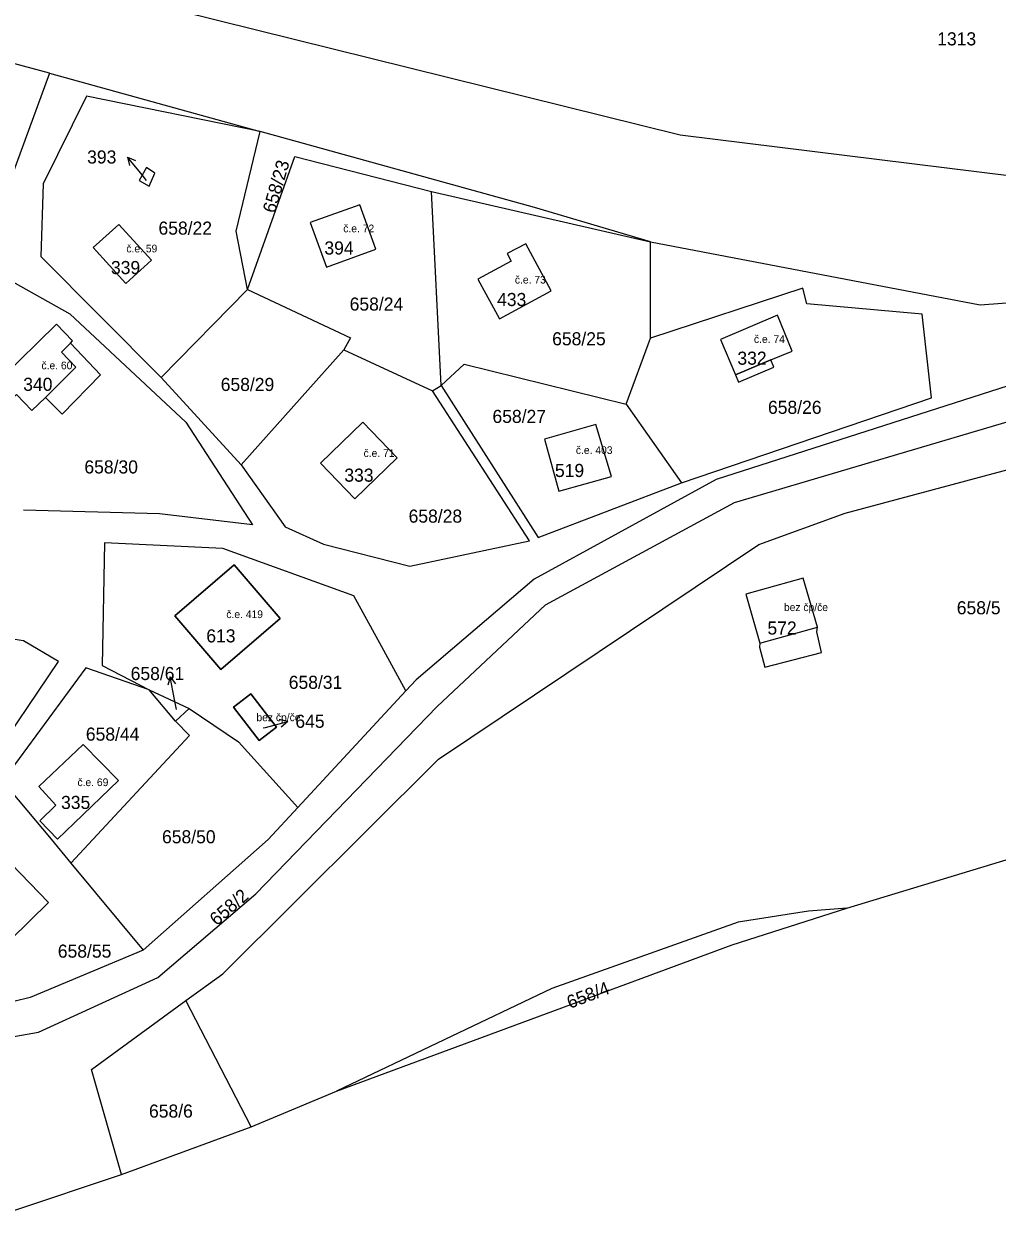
# Model space of a CAD drawing. Extents: x -887272 to -880188, y -1026687 to -1021896.
# Drawn here: x -883771.9 to -883645.6, y -1024180.1 to -1024025.9 of the extents above; entities that cross this region are included whole.
import ezdxf

# ---------------------------------------------------------------- set-up
doc = ezdxf.new("R2010")
doc.units = 0
for name, color, linetype in [('Definiční body', 7, 'Continuous'), ('Hranice parcel', 7, 'Continuous'), ('Parcelní čísla', 7, 'Continuous'), ('Polygon budovy', 7, 'Continuous'), ('Pop  PČ popisy', 7, 'Continuous'), ('Vnitřní kresba', 7, 'Continuous')]:
    doc.layers.add(name, color=color, linetype=linetype)

msp = doc.modelspace()

# ---------------------------------------------------------------- linework, layer by layer
at = {"layer": 'Hranice parcel'}
for p, q in [((-883768.62, -1024032.31), (-883786.49, -1024027.54)), ((-883768.62, -1024032.31), (-883741.24, -1024039.87)), ((-883719.01, -1024047.69), (-883690.56, -1024054.21)), ((-883717.76, -1024072.88), (-883719.01, -1024047.69)), ((-883690.57, -1024066.72), (-883690.56, -1024054.21)), ((-883732.64, -1024057.49), (-883726.22, -1024055.15)), ((-883758.68, -1024059.61), (-883755.37, -1024056.59)), ((-883754.09, -1024071.82), (-883742.91, -1024060.4)), ((-883693.72, -1024075.31), (-883690.57, -1024066.72)), ((-883730.38, -1024068.23), (-883743.71, -1024083.19)), ((-883730.38, -1024068.23), (-883718.88, -1024073.58)), ((-883754.09, -1024071.82), (-883743.71, -1024083.19)), ((-883718.88, -1024073.58), (-883717.76, -1024072.88)), ((-883693.72, -1024075.31), (-883686.57, -1024085.51)), ((-883725.46, -1024106.79), (-883729.08, -1024100.16)), ((-883722.33, -1024112.53), (-883725.46, -1024106.79)), ((-883755.65, -1024112.37), (-883750.48, -1024114.83)), ((-883752.25, -1024116.45), (-883755.65, -1024112.37)), ((-883722.33, -1024112.53), (-883736.35, -1024127.68)), ((-883750.48, -1024114.83), (-883752.25, -1024116.45)), ((-883750.48, -1024114.83), (-883744.05, -1024119.14)), ((-883744.05, -1024119.14), (-883736.35, -1024127.68)), ((-883765.84, -1024134.88), (-883756.44, -1024146.18)), ((-883756.44, -1024146.18), (-883771.09, -1024152.35)), ((-883771.09, -1024152.35), (-883776.38, -1024153.62)), ((-883742.43, -1024169.12), (-883750.88, -1024152.74)), ((-883742.43, -1024169.12), (-883731.34, -1024164.5)), ((-883759.24, -1024175.32), (-883742.43, -1024169.12))]:
    msp.add_line(p, q, dxfattribs=at)
for points in [[(-883751.85, -1024024.16), (-883686.7, -1024040.32), (-883639.5, -1024046.16), (-883608.39, -1024045.1)], [(-883768.62, -1024032.31), (-883776.16, -1024052.87), (-883778.5, -1024053.04), (-883793.12, -1024043.9), (-883786.49, -1024027.54)], [(-883741.24, -1024039.87), (-883763.79, -1024035.29), (-883769.42, -1024046.7), (-883769.72, -1024056.1), (-883754.09, -1024071.82)], [(-883742.91, -1024060.4), (-883744.38, -1024052.83), (-883741.24, -1024039.87)], [(-883690.56, -1024054.21), (-883705.64, -1024049.74), (-883741.24, -1024039.87)], [(-883742.91, -1024060.4), (-883736.76, -1024043.15), (-883719.01, -1024047.69)], [(-883756.02, -1024044.56), (-883756.96, -1024046.24), (-883755.66, -1024047), (-883754.92, -1024045.28), (-883756.02, -1024044.56)], [(-883726.22, -1024055.15), (-883728.32, -1024049.39), (-883734.77, -1024051.7), (-883732.64, -1024057.49)], [(-883755.37, -1024056.59), (-883759.61, -1024051.94), (-883762.92, -1024054.96), (-883758.68, -1024059.61)], [(-883708.66, -1024056.73), (-883712.97, -1024059.05), (-883710.18, -1024064.2), (-883703.46, -1024060.56), (-883706.77, -1024054.45), (-883709.2, -1024055.74), (-883708.66, -1024056.73)], [(-883690.56, -1024054.21), (-883647.79, -1024062.38), (-883637.46, -1024061.6)], [(-883774.14, -1024058.98), (-883765.97, -1024063.54), (-883750.88, -1024077.62), (-883742.25, -1024090.97), (-883754.31, -1024089.52), (-883771.96, -1024089.06)], [(-883846.21, -1024144.12), (-883816.92, -1024155.06), (-883797.46, -1024159.1), (-883785.24, -1024159.54), (-883770.02, -1024156.86), (-883754.54, -1024149.76), (-883741.82, -1024138.86), (-883718.28, -1024114.56), (-883704.22, -1024101.36), (-883679.66, -1024088.08), (-883640.76, -1024076.54), (-883629.62, -1024072.06), (-883617.24, -1024060.68)], [(-883742.91, -1024060.4), (-883729.52, -1024066.69), (-883730.38, -1024068.23)], [(-883686.57, -1024085.51), (-883654.07, -1024074.47), (-883655.32, -1024063.62), (-883670.29, -1024062.28), (-883670.78, -1024060.24), (-883690.57, -1024066.72)], [(-883637.46, -1024061.6), (-883637.26, -1024068), (-883643.06, -1024072.58), (-883682.06, -1024085.08), (-883705.66, -1024098.02), (-883721, -1024111.1), (-883722.33, -1024112.53)], [(-883679.54, -1024071.48), (-883679.14, -1024072.43), (-883674.54, -1024070.47), (-883674.93, -1024069.55), (-883672.16, -1024068.39), (-883674.07, -1024063.75), (-883681.48, -1024066.91), (-883679.54, -1024071.48)], [(-883773.25, -1024074.38), (-883772.9, -1024074.05), (-883770.89, -1024076.11), (-883769.13, -1024074.41), (-883766.95, -1024076.58), (-883761.97, -1024071.47), (-883765.87, -1024067.35), (-883765.62, -1024067.08), (-883767.68, -1024064.92), (-883774.9, -1024072), (-883773.24, -1024073.7), (-883773.59, -1024074.02), (-883773.25, -1024074.38)], [(-883717.76, -1024072.88), (-883714.76, -1024070.1), (-883693.72, -1024075.31)], [(-883750.88, -1024152.74), (-883746.1, -1024149.26), (-883718.1, -1024121.38), (-883676.52, -1024093.5), (-883665.32, -1024089.44), (-883615.24, -1024076.02), (-883604.08, -1024076.62), (-883602.76, -1024070.42), (-883510.71, -1024093.58), (-883510.26, -1024098.08)], [(-883717.76, -1024072.88), (-883705.16, -1024092.62), (-883686.57, -1024085.51)], [(-883743.71, -1024083.19), (-883738.02, -1024091.21), (-883733.04, -1024093.47), (-883721.8, -1024096.35), (-883706.27, -1024093.05), (-883718.88, -1024073.58)], [(-883727.93, -1024077.64), (-883733.43, -1024082.94), (-883728.96, -1024087.58), (-883723.46, -1024082.28), (-883727.93, -1024077.64)], [(-883704.35, -1024079.85), (-883702.47, -1024086.61), (-883695.65, -1024084.69), (-883697.67, -1024077.93), (-883704.35, -1024079.85)], [(-883729.08, -1024100.16), (-883746.09, -1024094.02), (-883761.45, -1024093.29), (-883761.77, -1024109.23), (-883755.65, -1024112.37)], [(-883746.34, -1024109.73), (-883752.31, -1024102.8), (-883744.62, -1024096.17), (-883738.64, -1024103.11), (-883746.34, -1024109.73)], [(-883675.74, -1024109.43), (-883668.37, -1024107.52), (-883668.98, -1024104.85), (-883668.91, -1024104.27), (-883670.74, -1024097.9), (-883678.19, -1024099.96), (-883676.38, -1024106.32), (-883676.42, -1024106.85), (-883675.74, -1024109.43)], [(-883665.07, -1024140.74), (-883601.32, -1024121.4), (-883513.54, -1024098.82), (-883510.26, -1024098.08)], [(-883789.37, -1024125.15), (-883776.68, -1024122.39), (-883767.41, -1024108.72), (-883771.96, -1024106.03), (-883791.15, -1024103.07)], [(-883755.65, -1024112.37), (-883763.88, -1024109.51), (-883774.69, -1024124.26)], [(-883741.4, -1024118.96), (-883744.71, -1024114.63), (-883742.45, -1024112.9), (-883739.14, -1024117.22), (-883741.4, -1024118.96)], [(-883765.84, -1024134.88), (-883750.41, -1024118.33), (-883752.25, -1024116.45)], [(-883767.57, -1024131.79), (-883765.4, -1024129.71), (-883759.62, -1024124.18), (-883764.22, -1024119.5), (-883769.99, -1024124.95), (-883767.76, -1024127.36), (-883769.86, -1024129.38), (-883767.57, -1024131.79)], [(-883774.69, -1024124.26), (-883768.39, -1024131.8), (-883765.84, -1024134.88)], [(-883736.35, -1024127.68), (-883740.2, -1024131.84), (-883756.44, -1024146.18)], [(-883773.62, -1024144.81), (-883768.71, -1024140), (-883773.56, -1024134.99)], [(-883731.34, -1024164.5), (-883679.95, -1024145.51), (-883665.07, -1024140.74)], [(-883665.07, -1024140.74), (-883670.06, -1024141.14), (-883679.17, -1024142.58), (-883703.4, -1024151.16), (-883731.34, -1024164.5)], [(-883759.24, -1024175.32), (-883763.16, -1024161.7), (-883750.88, -1024152.74)], [(-883850.59, -1024159.71), (-883845.76, -1024161.5), (-883773.48, -1024180.1), (-883759.24, -1024175.32)]]:
    msp.add_lwpolyline(points, dxfattribs=at)
at = {"layer": 'Polygon budovy'}
for points in [[(-883728.32, -1024049.39), (-883734.77, -1024051.7), (-883732.64, -1024057.49), (-883726.22, -1024055.15)], [(-883762.92, -1024054.96), (-883758.68, -1024059.61), (-883755.37, -1024056.59), (-883759.61, -1024051.94)], [(-883703.46, -1024060.56), (-883706.77, -1024054.45), (-883709.2, -1024055.74), (-883708.66, -1024056.73), (-883712.97, -1024059.05), (-883710.18, -1024064.2)], [(-883679.54, -1024071.48), (-883674.93, -1024069.55), (-883672.16, -1024068.39), (-883674.07, -1024063.75), (-883681.48, -1024066.91)], [(-883773.59, -1024074.02), (-883773.25, -1024074.38), (-883772.9, -1024074.05), (-883770.89, -1024076.11), (-883769.13, -1024074.41), (-883765.16, -1024070.5), (-883767.03, -1024068.53), (-883765.87, -1024067.35), (-883765.62, -1024067.08), (-883767.68, -1024064.92), (-883774.9, -1024072), (-883773.24, -1024073.7)], [(-883723.46, -1024082.28), (-883727.93, -1024077.64), (-883733.43, -1024082.94), (-883728.96, -1024087.58)], [(-883702.47, -1024086.61), (-883695.65, -1024084.69), (-883697.67, -1024077.93), (-883704.35, -1024079.85)], [(-883738.64, -1024103.11), (-883744.62, -1024096.17), (-883752.31, -1024102.8), (-883746.34, -1024109.73)], [(-883678.19, -1024099.96), (-883676.38, -1024106.32), (-883668.91, -1024104.27), (-883670.74, -1024097.9)], [(-883744.71, -1024114.63), (-883741.4, -1024118.96), (-883739.14, -1024117.22), (-883742.45, -1024112.9)], [(-883769.99, -1024124.95), (-883767.76, -1024127.36), (-883769.86, -1024129.38), (-883767.57, -1024131.79), (-883765.4, -1024129.71), (-883759.62, -1024124.18), (-883764.22, -1024119.5)], [(-883780.21, -1024138.05), (-883773.62, -1024144.81), (-883768.71, -1024140), (-883773.56, -1024134.99), (-883775.1, -1024136.47), (-883777.14, -1024134.64), (-883778.34, -1024133.34), (-883781.61, -1024136.5)]]:
    msp.add_lwpolyline(points, close=True, dxfattribs=at)
at = {"layer": 'Pop  PČ popisy'}
for p, q in [((-883756.58, -1024045.53), (-883758.47, -1024043.2)), ((-883758.47, -1024043.2), (-883757.45, -1024043.66)), ((-883758.47, -1024043.2), (-883758.23, -1024044.29)), ((-883756, -1024046.26), (-883756.58, -1024045.53)), ((-883752.92, -1024110.7), (-883753.22, -1024111.78)), ((-883752.35, -1024113.65), (-883752.92, -1024110.7)), ((-883752.92, -1024110.7), (-883752.24, -1024111.59)), ((-883752.09, -1024114.96), (-883752.35, -1024113.65)), ((-883737.67, -1024116.48), (-883738.77, -1024116.26)), ((-883740.85, -1024117.34), (-883740.57, -1024117.26)), ((-883740.57, -1024117.26), (-883737.67, -1024116.48)), ((-883737.67, -1024116.48), (-883738.51, -1024117.23))]:
    msp.add_line(p, q, dxfattribs=at)
at = {"layer": 'Vnitřní kresba'}
for p, q in [((-883765.87, -1024067.35), (-883767.03, -1024068.53)), ((-883767.03, -1024068.53), (-883765.16, -1024070.5)), ((-883674.93, -1024069.55), (-883679.54, -1024071.48)), ((-883765.16, -1024070.5), (-883769.13, -1024074.41)), ((-883676.38, -1024106.32), (-883668.91, -1024104.27))]:
    msp.add_line(p, q, dxfattribs=at)

# ---------------------------------------------------------------- texts
at = {"layer": 'Definiční body'}
for s, p in [('č.e. 72', (-883730.46, -1024052.97)), ('č.e. 59', (-883758.62, -1024055.58)), ('č.e. 73', (-883708.18, -1024059.63)), ('č.e. 74', (-883677.14, -1024067.34)), ('č.e. 60', (-883769.64, -1024070.76)), ('č.e. 403', (-883700.26, -1024081.76)), ('č.e. 71', (-883727.82, -1024082.15)), ('č.e. 419', (-883745.64, -1024103.07)), ('bez čp/če', (-883673.25, -1024102.16)), ('bez čp/če', (-883741.73, -1024116.46)), ('č.e. 69', (-883764.97, -1024124.89))]:
    msp.add_text(s, height=1, dxfattribs=at).set_placement(p)
at = {"layer": 'Parcelní čísla'}
for s, p in [('1313', (-883653.35, -1024028.7)), ('393', (-883763.71, -1024044.04)), ('658/22', (-883754.45, -1024053.28)), ('394', (-883732.91, -1024055.86)), ('339', (-883760.62, -1024058.4)), ('433', (-883710.49, -1024062.55)), ('658/24', (-883729.63, -1024063.14)), ('658/25', (-883703.34, -1024067.65)), ('332', (-883679.29, -1024070.17)), ('340', (-883772.01, -1024073.56)), ('658/29', (-883746.37, -1024073.58)), ('658/26', (-883675.32, -1024076.55)), ('658/27', (-883711.09, -1024077.73)), ('658/30', (-883764.07, -1024084.29)), ('333', (-883730.32, -1024085.36)), ('519', (-883702.98, -1024084.75)), ('658/28', (-883721.98, -1024090.68)), ('658/5', (-883650.81, -1024102.58)), ('572', (-883675.39, -1024105.21)), ('613', (-883748.24, -1024106.23)), ('658/61', (-883758.06, -1024111.12)), ('658/31', (-883737.54, -1024112.26)), ('645', (-883736.68, -1024117.32)), ('658/44', (-883763.88, -1024118.99)), ('335', (-883767.1, -1024127.86)), ('658/50', (-883753.99, -1024132.32)), ('658/55', (-883767.52, -1024147.17)), ('658/6', (-883755.68, -1024167.94))]:
    msp.add_text(s, height=1.7, dxfattribs=at).set_placement(p)
for s, rotation, p in [('658/23', 74, (-883739.33, -1024050.58)), ('658/2', 41, (-883746.89, -1024143.11)), ('658/4', 21, (-883701.03, -1024153.83))]:
    msp.add_text(s, height=1.7, rotation=rotation, dxfattribs=at).set_placement(p)

doc.saveas('drawing.dxf')
